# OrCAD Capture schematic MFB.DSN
size A
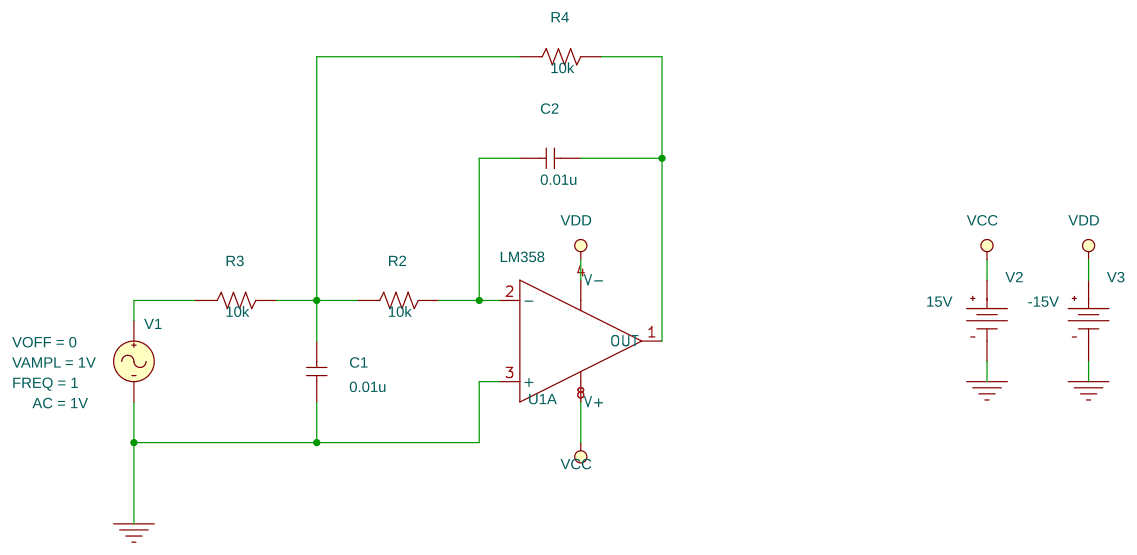
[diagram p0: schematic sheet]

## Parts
C1  0.01u  [cap196]
C2  0.01u  [cap196]
R2  10k  [AXRC05]
R3  10k  [AXRC05]
R4  10k  [AXRC05]
U1  LM358  [DIP1008W300L450]  (section A)
V1  VSIN
V2  VDC
V3  VDC

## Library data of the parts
C1 C2 = C
R2-R4 = R
U1 = LM358
V1 = VSIN: AC: 1V; FREQ: 1; VAMPL: 1V; VOFF: 0
V2 = VDC: DC: 15V
V3 = VDC: DC: -15V

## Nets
VCC: U1.8(V+) V2.0(+)
VDD: U1.4(V-) V3.0(+)
0: C1.1 U1.3(+) V1.2(-) V2.1(-) V3.1(-)
N01802: C1.2 R2.1 R3.2 R4.1
N01812: C2.1 R4.2 U1.1(OUT)
N01972: C2.2 R2.2 U1.2(-)
N02048: R3.1 V1.1(+)
